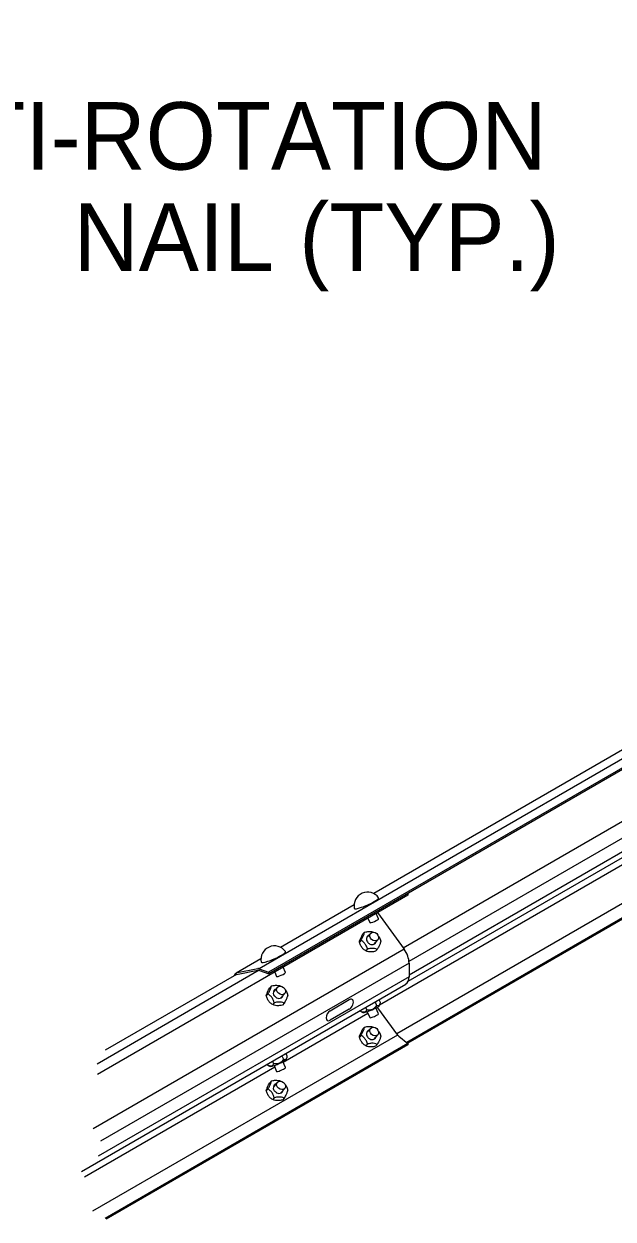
# Model space of a CAD drawing. Extents: x 99862 to 103680, y 99470 to 102076.
# Drawn here: x 101010.8 to 101150.6, y 100220.1 to 100503.4 of the extents above; entities that cross this region are included whole.
import ezdxf

# ---------------------------------------------------------------- set-up
doc = ezdxf.new("R2010")
doc.units = 0
for name, color, linetype in [('Level 20', 7, 'Continuous'), ('Level 27', 7, 'Continuous'), ('Level 5', 7, 'Continuous'), ('Level 7', 7, 'Continuous')]:
    doc.layers.add(name, color=color, linetype=linetype)

msp = doc.modelspace()

# ---------------------------------------------------------------- linework, layer by layer
at = {"layer": 'Level 27'}
for p, q in [((101450.83, 100503.38), (101093.78, 100297.23)), ((101175.93, 100342.52), (101066.64, 100279.43)), ((101175.93, 100340.45), (101068.83, 100278.61)), ((101175.93, 100340.01), (101068.89, 100278.21)), ((101175.93, 100327.71), (101100.79, 100284.33)), ((101175.93, 100323.74), (101102.14, 100281.14)), ((101175.93, 100320.5), (101102.16, 100277.91)), ((101175.93, 100317.44), (101095.16, 100270.81)), ((101101.97, 100276.49), (101175.93, 100319.19)), ((101175.93, 100308.24), (101099.26, 100263.97)), ((101175.93, 100304.85), (101101.62, 100261.94)), ((101175.93, 100304.54), (101101.84, 100261.77)), ((101101.89, 100296.89), (101028.24, 100254.37)), ((101101.84, 100297.24), (101101.89, 100296.89)), ((101089.11, 100294.54), (101071.7, 100284.48)), ((101094.7, 100292.74), (101100.98, 100284.07)), ((101100.98, 100284.07), (101027.26, 100241.5)), ((101102.16, 100280.78), (101028.98, 100238.53)), ((101067.03, 100281.79), (101061.13, 100278.38)), ((101102.16, 100280.78), (101102.16, 100277.54)), ((101066.64, 100279.05), (101028.17, 100256.84)), ((101102.16, 100277.54), (101028.41, 100234.96)), ((101061.2, 100278.04), (101030.1, 100260.09)), ((101061.2, 100278.04), (101066.31, 100279.07)), ((101061.49, 100278.52), (101066.26, 100279.47)), ((101066.64, 100279.43), (101068.83, 100278.61)), ((101066.7, 100279.02), (101068.89, 100278.21)), ((101068.83, 100278.61), (101068.89, 100278.21)), ((101024.43, 100231.35), (101101.36, 100275.76)), ((101083.44, 100269.47), (101087.99, 100272.1)), ((101092.39, 100268.83), (101072.31, 100257.24)), ((101087.99, 100269.85), (101083.44, 100267.22)), ((101094.69, 100270.16), (101099.45, 100263.71)), ((101099.45, 100263.71), (101027.09, 100221.93)), ((101099.71, 100263.44), (101101.89, 100261.73)), ((101101.89, 100261.73), (101030.03, 100220.23)), ((101101.84, 100261.39), (101030.29, 100220.08)), ((101101.89, 100261.73), (101101.84, 100261.39)), ((101070.31, 100256.08), (101025.19, 100230.04))]:
    msp.add_line(p, q, dxfattribs=at)
for centre, major_axis, ratio, start_param, end_param in [((101099.41, 100282.36), (1.94, -3.37), 0.57735, 0.785399, 1.748908), ((101062.85, 100275.41), (-1.71, 2.97), 0.57735, 6.090186, 6.721908), ((101066.82, 100278.17), (-0.71, 1.24), 0.57735, 5.674118, 6.090186), ((101066.88, 100277.77), (-0.71, 1.24), 0.57735, 5.674118, 6.090186), ((101099.41, 100279.13), (1.94, -3.37), 0.57735, 0, 0.785399), ((101087.99, 100270.97), (0.69, 1.19), 0.577351, 3.92699, 7.068583), ((101083.44, 100268.35), (0.69, 1.19), 0.577351, 0.785398, 3.92699), ((101099.83, 100264.15), (0.485, -0.84), 0.57735, 4.905662, 5.321456)]:
    msp.add_ellipse(centre, major_axis=major_axis, ratio=ratio, start_param=start_param, end_param=end_param, dxfattribs=at)
at = {"layer": 'Level 5'}
for p, q in [((101087.99, 100272.1), (101087.99, 100272.1)), ((101083.44, 100269.47), (101083.44, 100269.47))]:
    msp.add_line(p, q, dxfattribs=at)
msp.add_ellipse((101095.86, 100271.49), major_axis=(-1.48, 2.57), ratio=0.57735, start_param=1.701569, end_param=1.764069, dxfattribs=at)
at = {"layer": 'Level 7'}
for p, q in [((101092.37, 100291.4), (101092.83, 100290.35)), ((101094.93, 100291.27), (101094.37, 100292.55)), ((101090.77, 100286.17), (101090.38, 100285.72)), ((101091.59, 100288.11), (101091.21, 100287.66)), ((101093.02, 100287.8), (101092.06, 100286.72)), ((101093.79, 100285.2), (101094.74, 100286.29)), ((101092.28, 100284.11), (101091.9, 100283.67)), ((101094.62, 100284), (101094.24, 100283.56)), ((101070.29, 100278.65), (101070.74, 100277.6)), ((101072.85, 100278.52), (101072.29, 100279.8)), ((101069.51, 100275.36), (101069.12, 100274.91)), ((101070.93, 100275.05), (101069.98, 100273.97)), ((101068.69, 100273.42), (101068.3, 100272.97)), ((101071.7, 100272.45), (101072.66, 100273.54)), ((101094.09, 100271.56), (101094.45, 100270.73)), ((101095.01, 100272.1), (101095.28, 100271.5)), ((101070.2, 100271.36), (101069.81, 100270.92)), ((101072.54, 100271.25), (101072.15, 100270.81)), ((101090.53, 100269.51), (101090.6, 100269.37)), ((101090.64, 100269.34), (101091.16, 100269.05)), ((101091.85, 100270.27), (101092.11, 100269.67)), ((101092.22, 100269.24), (101092.83, 100267.84)), ((101094.93, 100268.76), (101094.32, 100270.16)), ((101095.15, 100270.79), (101095.21, 100271.03)), ((101090.77, 100263.66), (101090.38, 100263.21)), ((101091.59, 100265.6), (101091.21, 100265.15)), ((101093.02, 100265.29), (101092.06, 100264.21)), ((101093.79, 100262.69), (101094.74, 100263.78)), ((101092.28, 100261.6), (101091.9, 100261.16)), ((101094.62, 100261.49), (101094.24, 100261.05)), ((101069.77, 100257.52), (101070.03, 100256.92)), ((101072.01, 100258.81), (101072.37, 100257.98)), ((101072.85, 100256.01), (101072.24, 100257.41)), ((101072.93, 100259.35), (101073.19, 100258.75)), ((101073.07, 100258.04), (101073.13, 100258.28)), ((101068.45, 100256.76), (101068.51, 100256.62)), ((101068.56, 100256.59), (101069.08, 100256.3)), ((101070.13, 100256.49), (101070.74, 100255.09)), ((101069.51, 100252.85), (101069.12, 100252.4)), ((101070.93, 100252.54), (101069.98, 100251.46)), ((101068.69, 100250.91), (101068.3, 100250.46)), ((101070.2, 100248.85), (101069.81, 100248.41)), ((101071.7, 100249.94), (101072.66, 100251.03)), ((101072.54, 100248.74), (101072.15, 100248.3))]:
    msp.add_line(p, q, dxfattribs=at)
for centre in [(101092.34, 100294.35), (101070.25, 100281.6)]:
    msp.add_arc(centre, 3.23, 36.056, 191.0687, dxfattribs=at)
for centre, major_axis, start_param, end_param in [((101092.06, 100294.97), (2.89, 1.26), 4.227038, 6.317872), ((101092.06, 100294.97), (2.89, 1.26), 3.106906, 4.227038), ((101093.88, 100290.81), (1.05, 0.46), 3.141594, 6.283185), ((101069.98, 100282.22), (2.89, 1.26), 3.106906, 6.317872), ((101071.79, 100278.06), (1.05, 0.46), 3.141593, 6.283185), ((101093.14, 100269.96), (-2.01, -0.88), 0.119201, 1.837227), ((101093.88, 100268.3), (1.05, 0.46), 3.141593, 6.283187), ((101093.14, 100269.96), (-2.01, -0.88), 1.837227, 3.022391), ((101071.06, 100257.21), (-2.01, -0.88), 1.837227, 3.022388), ((101071.06, 100257.21), (-2.01, -0.88), 0.119201, 1.837227), ((101071.79, 100255.55), (1.05, 0.46), 3.141593, 6.283187)]:
    msp.add_ellipse(centre, major_axis=major_axis, ratio=0.156607, start_param=start_param, end_param=end_param, dxfattribs=at)
for centre in [(101093.88, 100287.05), (101071.79, 100274.3), (101093.88, 100264.54), (101071.79, 100251.79)]:
    msp.add_ellipse(centre, major_axis=(0.863, -0.758), ratio=0.801337, dxfattribs=at)
for points, degree in [([(101090.38, 100285.72), (101090.4, 100285.9), (101090.46, 100286.14), (101090.76, 100286.83), (101090.98, 100287.25), (101091.21, 100287.66)], 3), ([(101091.9, 100283.67), (101091.57, 100283.86), (101091.23, 100284.12), (101090.69, 100284.85), (101090.51, 100285.3), (101090.38, 100285.72)], 3), ([(101090.77, 100286.17), (101090.99, 100286.57), (101091.21, 100286.99), (101091.51, 100287.69), (101091.57, 100287.93), (101091.59, 100288.11)], 3), ([(101092.28, 100284.11), (101092.16, 100284.54), (101091.98, 100284.97), (101091.44, 100285.71), (101091.1, 100285.97), (101090.77, 100286.17)], 3), ([(101091.59, 100288.11), (101092.05, 100288.2), (101092.52, 100288.28), (101093.28, 100288.24), (101093.56, 100288.16), (101093.79, 100288.06)], 3), ([(101092.63, 100287.37), (101092.32, 100287.25), (101092.09, 100286.97), (101092, 100286.25), (101092.19, 100285.8), (101092.86, 100285.21), (101093.33, 100285.08), (101094.04, 100285.27), (101094.28, 100285.53), (101094.36, 100285.85)], 3), ([(101095.45, 100285.94), (101095.43, 100285.77), (101095.37, 100285.53), (101095.07, 100284.84), (101094.85, 100284.41), (101094.62, 100284)], 3), ([(101094.87, 100287.18), (101095.14, 100286.81), (101095.32, 100286.36), (101095.45, 100285.94)], 2), ([(101094.24, 100283.56), (101093.78, 100283.46), (101093.31, 100283.39), (101092.47, 100283.43), (101092.15, 100283.54), (101091.9, 100283.67)], 3), ([(101094.62, 100284), (101094.38, 100284.13), (101094.06, 100284.24), (101093.22, 100284.28), (101092.74, 100284.21), (101092.28, 100284.11)], 3), ([(101068.3, 100272.97), (101068.32, 100273.15), (101068.38, 100273.39), (101068.67, 100274.08), (101068.9, 100274.5), (101069.12, 100274.91)], 3), ([(101068.69, 100273.42), (101068.91, 100273.82), (101069.13, 100274.24), (101069.43, 100274.94), (101069.49, 100275.18), (101069.51, 100275.36)], 3), ([(101069.51, 100275.36), (101069.96, 100275.45), (101070.44, 100275.53), (101071.2, 100275.49), (101071.48, 100275.41), (101071.71, 100275.31)], 3), ([(101070.55, 100274.62), (101070.24, 100274.5), (101070.01, 100274.22), (101069.91, 100273.5), (101070.11, 100273.05), (101070.78, 100272.46), (101071.24, 100272.33), (101071.95, 100272.52), (101072.2, 100272.78), (101072.27, 100273.1)], 3), ([(101072.79, 100274.43), (101073.06, 100274.06), (101073.24, 100273.61), (101073.37, 100273.19)], 2), ([(101069.81, 100270.92), (101069.48, 100271.11), (101069.15, 100271.37), (101068.6, 100272.1), (101068.42, 100272.55), (101068.3, 100272.97)], 3), ([(101070.2, 100271.36), (101070.08, 100271.79), (101069.9, 100272.22), (101069.36, 100272.96), (101069.02, 100273.22), (101068.69, 100273.42)], 3), ([(101072.54, 100271.25), (101072.29, 100271.38), (101071.98, 100271.49), (101071.14, 100271.53), (101070.66, 100271.46), (101070.2, 100271.36)], 3), ([(101073.37, 100273.19), (101073.34, 100273.02), (101073.28, 100272.78), (101072.99, 100272.09), (101072.77, 100271.66), (101072.54, 100271.25)], 3), ([(101095.28, 100271.5), (101095.25, 100271.15), (101095.19, 100270.84), (101094.9, 100270.56), (101094.68, 100270.61), (101094.45, 100270.73)], 3), ([(101072.15, 100270.81), (101071.7, 100270.71), (101071.23, 100270.64), (101070.39, 100270.68), (101070.06, 100270.79), (101069.81, 100270.92)], 3), ([(101092.11, 100269.67), (101091.99, 100269.39), (101091.81, 100269.16), (101091.27, 100269.05), (101090.93, 100269.18), (101090.6, 100269.37)], 3), ([(101094.45, 100270.73), (101094.2, 100270.34), (101093.89, 100269.98), (101093.05, 100269.59), (101092.57, 100269.6), (101092.11, 100269.67)], 3), ([(101091.59, 100265.6), (101092.05, 100265.69), (101092.52, 100265.77), (101093.28, 100265.73), (101093.56, 100265.65), (101093.79, 100265.55)], 3), ([(101090.38, 100263.21), (101090.4, 100263.39), (101090.46, 100263.63), (101090.76, 100264.32), (101090.98, 100264.75), (101091.21, 100265.15)], 3), ([(101091.9, 100261.16), (101091.57, 100261.35), (101091.23, 100261.61), (101090.69, 100262.34), (101090.51, 100262.79), (101090.38, 100263.21)], 3), ([(101090.77, 100263.66), (101090.99, 100264.06), (101091.21, 100264.48), (101091.51, 100265.18), (101091.57, 100265.42), (101091.59, 100265.6)], 3), ([(101092.28, 100261.6), (101092.16, 100262.03), (101091.98, 100262.46), (101091.44, 100263.2), (101091.1, 100263.46), (101090.77, 100263.66)], 3), ([(101092.63, 100264.86), (101092.32, 100264.74), (101092.09, 100264.46), (101092, 100263.74), (101092.19, 100263.29), (101092.86, 100262.7), (101093.33, 100262.57), (101094.04, 100262.76), (101094.28, 100263.02), (101094.36, 100263.34)], 3), ([(101095.45, 100263.43), (101095.43, 100263.26), (101095.37, 100263.02), (101095.07, 100262.33), (101094.85, 100261.9), (101094.62, 100261.49)], 3), ([(101094.87, 100264.67), (101095.14, 100264.3), (101095.32, 100263.86), (101095.45, 100263.43)], 2), ([(101094.24, 100261.05), (101093.78, 100260.95), (101093.31, 100260.88), (101092.47, 100260.92), (101092.15, 100261.03), (101091.9, 100261.16)], 3), ([(101094.62, 100261.49), (101094.38, 100261.62), (101094.06, 100261.73), (101093.22, 100261.77), (101092.74, 100261.7), (101092.28, 100261.6)], 3), ([(101072.37, 100257.98), (101072.12, 100257.59), (101071.8, 100257.23), (101070.97, 100256.84), (101070.48, 100256.85), (101070.03, 100256.92)], 3), ([(101073.19, 100258.75), (101073.17, 100258.4), (101073.11, 100258.09), (101072.82, 100257.81), (101072.59, 100257.86), (101072.37, 100257.98)], 3), ([(101070.03, 100256.92), (101069.9, 100256.64), (101069.73, 100256.41), (101069.18, 100256.3), (101068.84, 100256.43), (101068.51, 100256.62)], 3), ([(101068.3, 100250.46), (101068.32, 100250.64), (101068.38, 100250.88), (101068.67, 100251.57), (101068.9, 100252), (101069.12, 100252.4)], 3), ([(101068.69, 100250.91), (101068.91, 100251.31), (101069.13, 100251.73), (101069.43, 100252.43), (101069.49, 100252.67), (101069.51, 100252.85)], 3), ([(101069.51, 100252.85), (101069.96, 100252.94), (101070.44, 100253.02), (101071.2, 100252.98), (101071.48, 100252.9), (101071.71, 100252.8)], 3), ([(101070.55, 100252.11), (101070.24, 100251.99), (101070.01, 100251.71), (101069.91, 100250.99), (101070.11, 100250.54), (101070.78, 100249.95), (101071.24, 100249.82), (101071.95, 100250.01), (101072.2, 100250.27), (101072.27, 100250.59)], 3), ([(101072.79, 100251.92), (101073.06, 100251.55), (101073.24, 100251.11), (101073.37, 100250.68)], 2), ([(101069.81, 100248.41), (101069.48, 100248.6), (101069.15, 100248.86), (101068.6, 100249.59), (101068.42, 100250.04), (101068.3, 100250.46)], 3), ([(101070.2, 100248.85), (101070.08, 100249.28), (101069.9, 100249.71), (101069.36, 100250.45), (101069.02, 100250.71), (101068.69, 100250.91)], 3), ([(101072.54, 100248.74), (101072.29, 100248.87), (101071.98, 100248.98), (101071.14, 100249.02), (101070.66, 100248.95), (101070.2, 100248.85)], 3), ([(101073.37, 100250.68), (101073.34, 100250.51), (101073.28, 100250.27), (101072.99, 100249.58), (101072.77, 100249.15), (101072.54, 100248.74)], 3), ([(101072.15, 100248.3), (101071.7, 100248.2), (101071.23, 100248.13), (101070.39, 100248.17), (101070.06, 100248.28), (101069.81, 100248.41)], 3)]:
    msp.add_open_spline(points, degree=degree, dxfattribs=at)

# ---------------------------------------------------------------- texts
at = {"layer": 'Level 20'}
for s, p in [('16d ANTI-ROTATION', (100926.73, 100468.83)), ('NAIL (TYP.)', (101022.59, 100444.83))]:
    msp.add_text(s, height=16, dxfattribs=at).set_placement(p)

doc.saveas('drawing.dxf')
